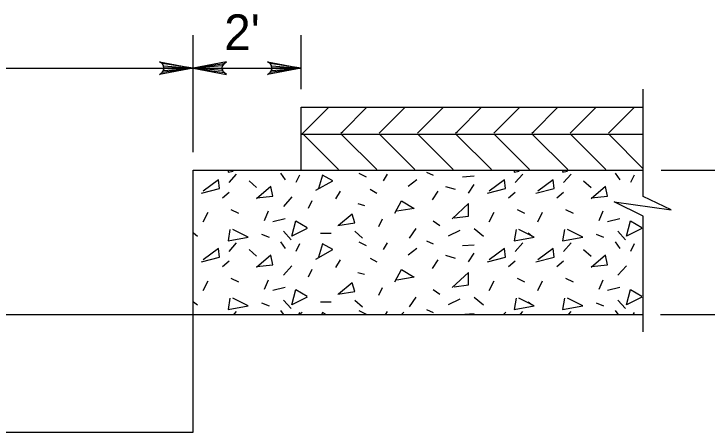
# Model space of a CAD drawing. Extents: x 3.47 to 10.73, y 1.11 to 10.92.
# Drawn here: x 7.328 to 8.494, y 10.215 to 10.918 of the extents above; entities that cross this region are included whole.
import ezdxf

# ---------------------------------------------------------------- set-up
doc = ezdxf.new("R2010")
doc.units = 0
for name, color, linetype in [('DETL-DIMS', 7, 'Continuous'), ('DETL-LINE', 7, 'Continuous'), ('DETL-NOTE', 7, 'Continuous'), ('DETL-PATT', 7, 'Continuous')]:
    doc.layers.add(name, color=color, linetype=linetype)

msp = doc.modelspace()

# ---------------------------------------------------------------- linework, layer by layer
at = {"layer": 'DETL-DIMS'}
for p, q in [((7.6291, 10.685), (7.6291, 10.882)), ((7.811, 10.7911), (7.811, 10.882)), ((6.2958, 10.8264), (7.6291, 10.8264)), ((7.6291, 10.8264), (7.811, 10.8264)), ((8.417, 10.6547), (8.6594, 10.6547)), ((8.4159, 10.4123), (8.6594, 10.4123))]:
    msp.add_line(p, q, dxfattribs=at)
for points in [[(7.6291, 10.8264), (7.5726, 10.8158), (7.577, 10.8188), (7.5792, 10.8226), (7.5799, 10.8264), (7.5792, 10.8302), (7.577, 10.8339), (7.5726, 10.837), (7.6291, 10.8264), (7.577, 10.8339), (7.5792, 10.8302), (7.6291, 10.8264), (7.5799, 10.8264), (7.5792, 10.8226), (7.6291, 10.8264), (7.577, 10.8188)], [(7.6291, 10.8264), (7.6856, 10.8158), (7.6813, 10.8188), (7.679, 10.8226), (7.6784, 10.8264), (7.679, 10.8302), (7.6813, 10.8339), (7.6856, 10.837), (7.6291, 10.8264), (7.6813, 10.8339), (7.679, 10.8302), (7.6291, 10.8264), (7.6784, 10.8264), (7.679, 10.8226), (7.6291, 10.8264), (7.6813, 10.8188)], [(7.811, 10.8264), (7.7545, 10.8158), (7.7588, 10.8188), (7.7611, 10.8226), (7.7617, 10.8264), (7.7611, 10.8302), (7.7588, 10.8339), (7.7545, 10.837), (7.811, 10.8264), (7.7588, 10.8339), (7.7611, 10.8302), (7.811, 10.8264), (7.7617, 10.8264), (7.7611, 10.8226), (7.811, 10.8264), (7.7588, 10.8188)]]:
    msp.add_lwpolyline(points, dxfattribs=at)
at = {"layer": 'DETL-LINE'}
for p, q in [((8.3867, 10.6107), (8.3867, 10.7911)), ((7.811, 10.7608), (8.3867, 10.7608)), ((7.811, 10.6547), (7.811, 10.7608)), ((7.811, 10.7153), (8.3867, 10.7153)), ((7.6291, 10.2145), (7.6291, 10.6547)), ((7.6291, 10.6547), (8.3867, 10.6547)), ((8.3867, 10.3829), (8.3867, 10.5774)), ((6.2958, 10.4123), (7.6291, 10.4123)), ((7.6291, 10.4123), (8.3867, 10.4123)), ((6.2958, 10.2145), (7.6291, 10.2145))]:
    msp.add_line(p, q, dxfattribs=at)
msp.add_lwpolyline([(8.3867, 10.5774), (8.3376, 10.6014), (8.4337, 10.5884), (8.3867, 10.6107)], dxfattribs=at)
at = {"layer": 'DETL-PATT'}
for p, q in [((7.8122, 10.7153), (7.857, 10.7601)), ((7.8811, 10.7199), (7.9213, 10.7601)), ((7.9453, 10.7199), (7.9856, 10.7601)), ((8.0096, 10.7199), (8.0499, 10.7601)), ((8.0739, 10.7199), (8.1142, 10.7601)), ((8.1382, 10.7199), (8.1785, 10.7601)), ((8.2025, 10.7199), (8.2427, 10.7601)), ((8.2667, 10.7199), (8.307, 10.7601)), ((8.331, 10.7199), (8.3713, 10.7601)), ((7.874, 10.6558), (7.8145, 10.7153)), ((7.8149, 10.718), (7.8168, 10.7199)), ((7.878, 10.7168), (7.8811, 10.7199)), ((7.8803, 10.7138), (7.8797, 10.7144)), ((7.9383, 10.6558), (7.8803, 10.7138)), ((7.9423, 10.7168), (7.9453, 10.7199)), ((7.9446, 10.7138), (7.944, 10.7144)), ((8.0026, 10.6558), (7.9446, 10.7138)), ((8.0066, 10.7168), (8.0096, 10.7199)), ((8.0089, 10.7138), (8.0083, 10.7144)), ((8.0668, 10.6558), (8.0089, 10.7138)), ((8.0708, 10.7168), (8.0739, 10.7199)), ((8.0731, 10.7138), (8.0725, 10.7144)), ((8.1311, 10.6558), (8.0731, 10.7138)), ((8.1351, 10.7168), (8.1382, 10.7199)), ((8.1374, 10.7138), (8.1368, 10.7144)), ((8.1954, 10.6558), (8.1374, 10.7138)), ((8.1994, 10.7168), (8.2025, 10.7199)), ((8.2017, 10.7138), (8.2011, 10.7144)), ((8.2597, 10.6558), (8.2017, 10.7138)), ((8.2637, 10.7168), (8.2667, 10.7199)), ((8.266, 10.7138), (8.2654, 10.7144)), ((8.324, 10.6558), (8.266, 10.7138)), ((8.328, 10.7168), (8.331, 10.7199)), ((8.3303, 10.7138), (8.3297, 10.7144)), ((8.3867, 10.6573), (8.3303, 10.7138)), ((8.0218, 10.6516), (8.0331, 10.6467)), ((7.6897, 10.6339), (7.7025, 10.6483)), ((7.7763, 10.6499), (7.7844, 10.6387)), ((7.8084, 10.6467), (7.802, 10.6339)), ((7.9079, 10.6499), (7.9207, 10.6435)), ((7.9496, 10.6371), (7.9561, 10.6483)), ((8.0828, 10.6435), (8.1021, 10.6451)), ((8.1711, 10.6339), (8.1839, 10.6483)), ((8.2527, 10.6339), (8.2656, 10.6483)), ((8.3394, 10.6499), (8.3474, 10.6387)), ((8.3715, 10.6467), (8.365, 10.6339)), ((7.7234, 10.6371), (7.7362, 10.6259)), ((8.0058, 10.6387), (7.9914, 10.6275)), ((8.0539, 10.6275), (8.07, 10.6227)), ((8.0924, 10.6163), (8.1021, 10.6307)), ((8.2864, 10.6371), (8.2993, 10.6259)), ((7.6785, 10.6082), (7.6897, 10.6179)), ((7.8694, 10.6066), (7.8774, 10.6195)), ((7.9272, 10.6227), (7.9384, 10.6163)), ((8.0411, 10.6195), (8.0315, 10.605)), ((8.1598, 10.6082), (8.1711, 10.6179)), ((8.2415, 10.6082), (8.2527, 10.6179)), ((7.7956, 10.6098), (7.7812, 10.5938)), ((7.8293, 10.6034), (7.8229, 10.5906)), ((7.9063, 10.5986), (7.9175, 10.5954)), ((7.6464, 10.5681), (7.6544, 10.5842)), ((7.6929, 10.589), (7.7057, 10.5826)), ((7.7555, 10.5858), (7.7491, 10.5697)), ((8.1277, 10.5681), (8.1358, 10.5842)), ((8.1743, 10.589), (8.1871, 10.5826)), ((8.2094, 10.5681), (8.2174, 10.5842)), ((8.2559, 10.589), (8.2688, 10.5826)), ((8.3185, 10.5858), (8.3121, 10.5697)), ((7.7844, 10.5729), (7.7635, 10.5681)), ((7.9416, 10.5601), (7.948, 10.5729)), ((8.0331, 10.5697), (8.0443, 10.5617)), ((8.3474, 10.5729), (8.3265, 10.5681)), ((7.6302, 10.5493), (7.6367, 10.544)), ((7.7442, 10.5473), (7.7571, 10.5424)), ((7.7812, 10.5521), (7.794, 10.5376)), ((7.8437, 10.5489), (7.8614, 10.5489)), ((7.9015, 10.5521), (7.9143, 10.5408)), ((8.0042, 10.5569), (7.993, 10.5408)), ((8.078, 10.5537), (8.0587, 10.544)), ((8.1021, 10.5569), (8.1181, 10.544)), ((8.1932, 10.5493), (8.1998, 10.544)), ((8.3073, 10.5473), (8.3201, 10.5424)), ((8.3442, 10.5521), (8.357, 10.5376)), ((7.7763, 10.5344), (7.7844, 10.5232)), ((7.9079, 10.5344), (7.9207, 10.528)), ((8.0218, 10.536), (8.0331, 10.5312)), ((8.3394, 10.5344), (8.3474, 10.5232)), ((7.6897, 10.5184), (7.7025, 10.5328)), ((7.8084, 10.5312), (7.802, 10.5184)), ((7.9496, 10.5216), (7.9561, 10.5328)), ((8.0058, 10.5232), (7.9914, 10.512)), ((8.0828, 10.528), (8.1021, 10.5296)), ((8.1711, 10.5184), (8.1839, 10.5328)), ((8.2527, 10.5184), (8.2656, 10.5328)), ((8.3715, 10.5312), (8.365, 10.5184)), ((7.7234, 10.5216), (7.7362, 10.5103)), ((8.0539, 10.512), (8.07, 10.5071)), ((8.0924, 10.5007), (8.1021, 10.5152)), ((8.2864, 10.5216), (8.2993, 10.5103)), ((7.6785, 10.4927), (7.6897, 10.5023)), ((7.8694, 10.4911), (7.8774, 10.5039)), ((7.9272, 10.5071), (7.9384, 10.5007)), ((8.0411, 10.5039), (8.0315, 10.4895)), ((8.1598, 10.4927), (8.1711, 10.5023)), ((8.2415, 10.4927), (8.2527, 10.5023)), ((7.7956, 10.4943), (7.7812, 10.4783)), ((7.8293, 10.4879), (7.8229, 10.475)), ((8.3586, 10.4943), (8.3442, 10.4783)), ((7.9063, 10.4831), (7.9175, 10.4799)), ((7.6464, 10.4526), (7.6544, 10.4686)), ((7.6929, 10.4734), (7.7057, 10.467)), ((7.7555, 10.4702), (7.7491, 10.4542)), ((8.1277, 10.4526), (8.1358, 10.4686)), ((8.1743, 10.4734), (8.1871, 10.467)), ((8.2094, 10.4526), (8.2174, 10.4686)), ((8.2559, 10.4734), (8.2688, 10.467)), ((8.3185, 10.4702), (8.3121, 10.4542)), ((7.7844, 10.4574), (7.7635, 10.4526)), ((7.9416, 10.4446), (7.948, 10.4574)), ((8.0331, 10.4542), (8.0443, 10.4462)), ((8.3474, 10.4574), (8.3265, 10.4526)), ((8.0042, 10.4413), (7.993, 10.4253)), ((8.1021, 10.4413), (8.1181, 10.4285)), ((7.6302, 10.4337), (7.6367, 10.4285)), ((7.7442, 10.4317), (7.7571, 10.4269)), ((7.7812, 10.4365), (7.794, 10.4221)), ((7.8437, 10.4333), (7.8614, 10.4333)), ((7.9015, 10.4365), (7.9143, 10.4253)), ((8.078, 10.4381), (8.0587, 10.4285)), ((8.1932, 10.4337), (8.1998, 10.4285)), ((8.3073, 10.4317), (8.3201, 10.4269)), ((8.3442, 10.4365), (8.357, 10.4221)), ((7.7763, 10.4189), (7.7807, 10.4128)), ((7.9079, 10.4189), (7.9202, 10.4128)), ((8.0218, 10.4205), (8.0331, 10.4157)), ((8.3394, 10.4189), (8.3437, 10.4128)), ((7.6985, 10.4128), (7.7025, 10.4173)), ((7.8084, 10.4157), (7.807, 10.4128)), ((7.8087, 10.4123), (7.8126, 10.4162)), ((7.9535, 10.4128), (7.9561, 10.4173)), ((7.9801, 10.4123), (7.984, 10.4162)), ((8.0864, 10.4128), (8.1021, 10.4141)), ((8.1515, 10.4123), (8.1554, 10.4162)), ((8.1799, 10.4128), (8.1839, 10.4173)), ((8.2615, 10.4128), (8.2656, 10.4173)), ((8.3715, 10.4157), (8.37, 10.4128))]:
    msp.add_line(p, q, dxfattribs=at)
for points in [[(7.6884, 10.6531), (7.6881, 10.6516), (7.6965, 10.6531)], [(8.1697, 10.6531), (8.1695, 10.6516), (8.1778, 10.6531)], [(8.2514, 10.6531), (8.2511, 10.6516), (8.2595, 10.6531)], [(7.8357, 10.6211), (7.8646, 10.6371), (7.8469, 10.6467), (7.8405, 10.6243)], [(7.6432, 10.6163), (7.6736, 10.6243), (7.672, 10.6387), (7.6464, 10.6195)], [(7.7362, 10.6082), (7.7635, 10.6114), (7.7603, 10.6275), (7.7362, 10.6066)], [(8.1245, 10.6163), (8.155, 10.6243), (8.1534, 10.6387), (8.1277, 10.6195)], [(8.2062, 10.6163), (8.2367, 10.6243), (8.2351, 10.6387), (8.2094, 10.6195)], [(8.2993, 10.6082), (8.3265, 10.6114), (8.3233, 10.6275), (8.2993, 10.6066)], [(7.9689, 10.5826), (7.9801, 10.6034), (8.001, 10.5906), (7.9721, 10.5858)], [(8.0684, 10.5745), (8.0924, 10.5777), (8.0924, 10.5986), (8.0652, 10.5729)], [(7.8726, 10.5617), (7.9015, 10.5665), (7.8967, 10.5809), (7.8742, 10.5617)], [(7.8213, 10.5569), (7.7956, 10.544), (7.802, 10.5697), (7.8213, 10.5585)], [(8.3843, 10.5569), (8.3586, 10.544), (8.365, 10.5697), (8.3843, 10.5585)], [(7.6913, 10.5553), (7.6881, 10.536), (7.7218, 10.5424), (7.6961, 10.5553)], [(8.1727, 10.5553), (8.1695, 10.536), (8.2032, 10.5424), (8.1775, 10.5553)], [(8.2543, 10.5553), (8.2511, 10.536), (8.2848, 10.5424), (8.2591, 10.5553)], [(7.6432, 10.5007), (7.6736, 10.5087), (7.672, 10.5232), (7.6464, 10.5039)], [(7.8357, 10.5055), (7.8646, 10.5216), (7.8469, 10.5312), (7.8405, 10.5087)], [(8.1245, 10.5007), (8.155, 10.5087), (8.1534, 10.5232), (8.1277, 10.5039)], [(8.2062, 10.5007), (8.2367, 10.5087), (8.2351, 10.5232), (8.2094, 10.5039)], [(7.7362, 10.4927), (7.7635, 10.4959), (7.7603, 10.512), (7.7362, 10.4911)], [(8.2993, 10.4927), (8.3265, 10.4959), (8.3233, 10.512), (8.2993, 10.4911)], [(7.9689, 10.467), (7.9801, 10.4879), (8.001, 10.475), (7.9721, 10.4702)], [(8.0684, 10.459), (8.0924, 10.4622), (8.0924, 10.4831), (8.0652, 10.4574)], [(7.8726, 10.4462), (7.9015, 10.451), (7.8967, 10.4654), (7.8742, 10.4462)], [(7.8213, 10.4413), (7.7956, 10.4285), (7.802, 10.4542), (7.8213, 10.443)], [(8.3843, 10.4413), (8.3586, 10.4285), (8.365, 10.4542), (8.3843, 10.443)], [(7.6913, 10.4397), (7.6881, 10.4205), (7.7218, 10.4269), (7.6961, 10.4397)], [(8.1727, 10.4397), (8.1695, 10.4205), (8.2032, 10.4269), (8.1775, 10.4397)], [(8.2543, 10.4397), (8.2511, 10.4205), (8.2848, 10.4269), (8.2591, 10.4397)], [(7.8523, 10.4128), (7.8469, 10.4157), (7.8461, 10.4128)]]:
    msp.add_lwpolyline(points, dxfattribs=at)

# ---------------------------------------------------------------- texts
at = {"layer": 'DETL-NOTE'}
msp.add_text("2'", height=0.06, dxfattribs=at).set_placement((7.6816, 10.8567))

doc.saveas('drawing.dxf')
